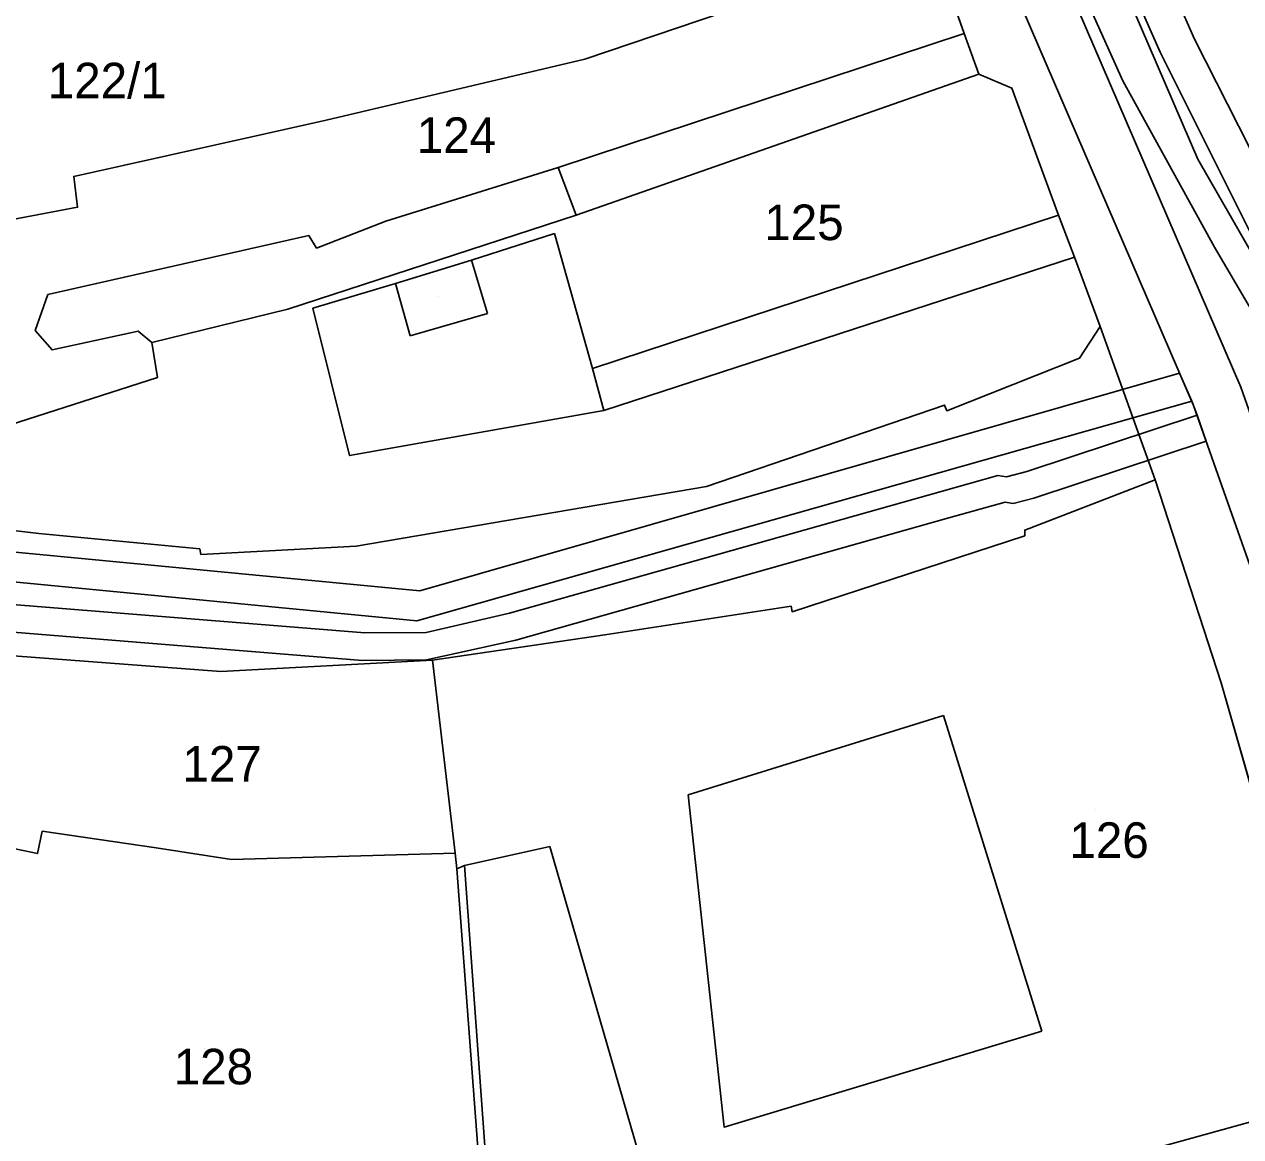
# Model space of a CAD drawing. Extents: x -263423 to -261326, y -1240067 to -1237864.
# Drawn here: x -262808 to -262739.6, y -1239820.5 to -1239757.9 of the extents above; entities that cross this region are included whole.
import ezdxf

# ---------------------------------------------------------------- set-up
doc = ezdxf.new("R2010")
doc.units = 0
for name, color, linetype in [('body_kn', 7, 'Continuous'), ('kladpar_druhypozemkov', 7, 'Continuous'), ('kladpar_hranice', 7, 'Continuous'), ('kladpar_parcelnecisla', 7, 'Continuous'), ('kladpar_plochy', 7, 'Continuous'), ('tarchy_linie', 7, 'Continuous'), ('zappar_hrandruhpozemk', 7, 'Continuous')]:
    doc.layers.add(name, color=color, linetype=linetype)

msp = doc.modelspace()

# ---------------------------------------------------------------- linework, layer by layer
at = {"layer": 'body_kn'}
for p, q in [((-262755.17, -1239758.45), (-262755.17, -1239758.45)), ((-262755.17, -1239758.45), (-262755.17, -1239758.45)), ((-262742.22, -1239758.77), (-262742.22, -1239758.77)), ((-262776.5, -1239759.89), (-262776.5, -1239759.89)), ((-262776.5, -1239759.89), (-262776.5, -1239759.89)), ((-262744.15, -1239759.51), (-262744.15, -1239759.51)), ((-262754.35, -1239760.75), (-262754.35, -1239760.75)), ((-262746.26, -1239761.11), (-262746.26, -1239761.11)), ((-262752.5, -1239761.52), (-262752.5, -1239761.52)), ((-262791.05, -1239763.32), (-262791.05, -1239763.32)), ((-262794.48, -1239764.1), (-262794.48, -1239764.1)), ((-262778, -1239765.99), (-262778, -1239765.99)), ((-262778, -1239765.99), (-262778, -1239765.99)), ((-262742.03, -1239765.52), (-262742.03, -1239765.52)), ((-262805.24, -1239766.49), (-262805.24, -1239766.49)), ((-262805.03, -1239768.22), (-262805.03, -1239768.22)), ((-262776.99, -1239768.67), (-262776.99, -1239768.67)), ((-262776.99, -1239768.67), (-262776.99, -1239768.67)), ((-262749.86, -1239768.67), (-262749.86, -1239768.67)), ((-262787.7, -1239769), (-262787.7, -1239769)), ((-262792.03, -1239769.81), (-262792.03, -1239769.81)), ((-262778.21, -1239769.69), (-262778.21, -1239769.69)), ((-262791.59, -1239770.52), (-262791.59, -1239770.52)), ((-262741.1, -1239770.47), (-262741.1, -1239770.47)), ((-262782.87, -1239771.19), (-262782.87, -1239771.19)), ((-262748.97, -1239771.03), (-262748.97, -1239771.03)), ((-262748.97, -1239771.03), (-262748.97, -1239771.03)), ((-262787.14, -1239772.51), (-262787.14, -1239772.51)), ((-262787.14, -1239772.51), (-262787.14, -1239772.51)), ((-262806.7, -1239773.12), (-262806.7, -1239773.12)), ((-262793.2, -1239773.95), (-262793.2, -1239773.95)), ((-262791.8, -1239773.89), (-262791.8, -1239773.89)), ((-262791.8, -1239773.89), (-262791.8, -1239773.89)), ((-262781.98, -1239774.19), (-262781.98, -1239774.19)), ((-262747.52, -1239774.93), (-262747.52, -1239774.93)), ((-262807.41, -1239775.16), (-262807.41, -1239775.16)), ((-262801.61, -1239775.18), (-262801.61, -1239775.18)), ((-262786.32, -1239775.45), (-262786.32, -1239775.45)), ((-262806.46, -1239776.24), (-262806.46, -1239776.24)), ((-262800.85, -1239775.82), (-262800.85, -1239775.82)), ((-262748.68, -1239776.7), (-262748.68, -1239776.7)), ((-262776.07, -1239777.28), (-262776.07, -1239777.28)), ((-262743.06, -1239777.55), (-262743.06, -1239777.55)), ((-262800.54, -1239777.8), (-262800.54, -1239777.8)), ((-262775.44, -1239779.64), (-262775.44, -1239779.64)), ((-262756.27, -1239779.34), (-262756.27, -1239779.34)), ((-262756.14, -1239779.66), (-262756.14, -1239779.66)), ((-262742.38, -1239779.12), (-262742.38, -1239779.12)), ((-262742.27, -1239779.37), (-262742.27, -1239779.37)), ((-262742.08, -1239779.91), (-262742.08, -1239779.91)), ((-262741.57, -1239781.37), (-262741.57, -1239781.37)), ((-262789.73, -1239782.18), (-262789.73, -1239782.18)), ((-262751.64, -1239783.07), (-262751.64, -1239783.07)), ((-262753.28, -1239783.31), (-262753.28, -1239783.31)), ((-262752.8, -1239783.37), (-262752.8, -1239783.37)), ((-262744.44, -1239783.54), (-262744.44, -1239783.54)), ((-262769.66, -1239783.93), (-262769.66, -1239783.93)), ((-262756.46, -1239784.2), (-262756.46, -1239784.2)), ((-262752.86, -1239784.8), (-262752.86, -1239784.8)), ((-262752.41, -1239784.87), (-262752.41, -1239784.87)), ((-262751.25, -1239784.57), (-262751.25, -1239784.57)), ((-262756.04, -1239785.69), (-262756.04, -1239785.69)), ((-262807.2, -1239786.56), (-262807.2, -1239786.56)), ((-262751.77, -1239786.37), (-262751.77, -1239786.37)), ((-262751.77, -1239786.69), (-262751.77, -1239786.69)), ((-262751.77, -1239786.69), (-262751.77, -1239786.69)), ((-262798.16, -1239787.43), (-262798.16, -1239787.43)), ((-262798.09, -1239787.75), (-262798.09, -1239787.75)), ((-262789.36, -1239787.28), (-262789.36, -1239787.28)), ((-262785.79, -1239789.79), (-262785.79, -1239789.79)), ((-262764.91, -1239790.65), (-262764.91, -1239790.65)), ((-262780.73, -1239791.05), (-262780.73, -1239791.05)), ((-262764.85, -1239790.96), (-262764.85, -1239790.96)), ((-262785.95, -1239791.48), (-262785.95, -1239791.48)), ((-262788.88, -1239792.15), (-262788.88, -1239792.15)), ((-262785.42, -1239792.12), (-262785.42, -1239792.12)), ((-262780.39, -1239792.56), (-262780.39, -1239792.56)), ((-262775.37, -1239792.25), (-262775.37, -1239792.25)), ((-262789, -1239793.7), (-262789, -1239793.7)), ((-262785.41, -1239793.67), (-262785.41, -1239793.67)), ((-262785.06, -1239793.68), (-262785.06, -1239793.68)), ((-262796.97, -1239794.32), (-262796.97, -1239794.32)), ((-262796.97, -1239794.32), (-262796.97, -1239794.32)), ((-262740.72, -1239794.96), (-262740.72, -1239794.96)), ((-262756.34, -1239796.8), (-262756.34, -1239796.8)), ((-262770.69, -1239801.26), (-262770.69, -1239801.26)), ((-262770.69, -1239801.26), (-262770.69, -1239801.26)), ((-262807.01, -1239803.29), (-262807.01, -1239803.29)), ((-262800.61, -1239804.24), (-262800.61, -1239804.24)), ((-262778.47, -1239804.16), (-262778.47, -1239804.16)), ((-262807.28, -1239804.56), (-262807.28, -1239804.56)), ((-262796.38, -1239804.89), (-262796.38, -1239804.89)), ((-262796.38, -1239804.89), (-262796.38, -1239804.89)), ((-262783.8, -1239804.54), (-262783.8, -1239804.54)), ((-262783.7, -1239805.41), (-262783.7, -1239805.41)), ((-262783.7, -1239805.41), (-262783.7, -1239805.41)), ((-262783.26, -1239805.22), (-262783.26, -1239805.22)), ((-262750.8, -1239814.54), (-262750.8, -1239814.54)), ((-262768.66, -1239819.94), (-262768.66, -1239819.94))]:
    msp.add_line(p, q, dxfattribs=at)
at = {"layer": 'kladpar_druhypozemkov'}
for p, q in [((-262802.68, -1239759.77), (-262802.68, -1239759.77)), ((-262783.98, -1239762.87), (-262783.98, -1239762.87)), ((-262764.48, -1239768.17), (-262764.48, -1239768.17)), ((-262784.73, -1239773.22), (-262784.73, -1239773.22)), ((-262797.08, -1239798.39), (-262797.08, -1239798.39)), ((-262747.78, -1239802.1), (-262747.78, -1239802.1)), ((-262797.88, -1239815.5), (-262797.88, -1239815.5))]:
    msp.add_line(p, q, dxfattribs=at)
at = {"layer": 'kladpar_hranice'}
for points in [[(-262819.26, -1239758.47), (-262800.19, -1239752.89), (-262797.7, -1239752.2), (-262787.75, -1239749.25), (-262787.43, -1239749.13), (-262782.39, -1239747.56), (-262764.98, -1239741.91), (-262761.47, -1239740.71), (-262759.7, -1239745.5), (-262758.95, -1239747.67), (-262756.99, -1239753.28), (-262776.5, -1239759.89), (-262791.05, -1239763.32), (-262794.48, -1239764.1), (-262805.24, -1239766.49), (-262805.03, -1239768.22), (-262813.14, -1239769.76), (-262811.51, -1239781.32), (-262813.94, -1239781.75), (-262815.81, -1239772.06), (-262819.26, -1239758.47)], [(-262776.5, -1239759.89), (-262756.99, -1239753.28), (-262755.17, -1239758.45), (-262754.35, -1239760.75), (-262776.99, -1239768.67), (-262793.2, -1239773.95), (-262800.85, -1239775.82), (-262800.54, -1239777.8), (-262811.51, -1239781.32), (-262813.14, -1239769.76), (-262805.03, -1239768.22), (-262805.24, -1239766.49), (-262794.48, -1239764.1), (-262791.05, -1239763.32), (-262776.5, -1239759.89)], [(-262737.14, -1239807.47), (-262740.72, -1239794.96), (-262744.44, -1239783.54), (-262747.52, -1239774.93), (-262748.97, -1239771.03), (-262749.86, -1239768.67), (-262752.5, -1239761.52), (-262754.35, -1239760.75), (-262755.17, -1239758.45), (-262756.99, -1239753.28)], [(-262776.99, -1239768.67), (-262754.35, -1239760.75), (-262752.5, -1239761.52), (-262749.86, -1239768.67), (-262748.97, -1239771.03), (-262747.52, -1239774.93), (-262748.68, -1239776.7), (-262756.14, -1239779.66), (-262756.27, -1239779.34), (-262769.66, -1239783.93), (-262789.36, -1239787.28), (-262798.09, -1239787.75), (-262798.16, -1239787.43), (-262807.2, -1239786.56), (-262818.47, -1239785.24)], [(-262811.51, -1239781.32), (-262800.54, -1239777.8), (-262800.85, -1239775.82), (-262793.2, -1239773.95), (-262776.99, -1239768.67)], [(-262818.47, -1239785.24), (-262807.2, -1239786.56), (-262798.16, -1239787.43), (-262798.09, -1239787.75), (-262789.36, -1239787.28), (-262769.66, -1239783.93), (-262756.27, -1239779.34), (-262756.14, -1239779.66), (-262748.68, -1239776.7), (-262747.52, -1239774.93), (-262744.44, -1239783.54), (-262751.77, -1239786.37), (-262751.77, -1239786.69), (-262764.85, -1239790.96), (-262764.91, -1239790.65), (-262775.37, -1239792.25), (-262785.06, -1239793.68), (-262796.97, -1239794.32), (-262808.63, -1239793.44)], [(-262751.77, -1239786.69), (-262751.77, -1239786.37), (-262744.44, -1239783.54), (-262740.72, -1239794.96), (-262737.14, -1239807.47), (-262733.56, -1239818.12), (-262770.29, -1239828.28), (-262771.57, -1239828.53), (-262775.26, -1239828.89), (-262777.05, -1239829.08), (-262781.89, -1239829.56), (-262782.25, -1239824.59), (-262783.7, -1239805.41), (-262783.8, -1239804.54), (-262785.06, -1239793.68), (-262775.37, -1239792.25), (-262764.91, -1239790.65), (-262764.85, -1239790.96), (-262751.77, -1239786.69)], [(-262796.97, -1239794.32), (-262785.06, -1239793.68), (-262783.8, -1239804.54), (-262796.38, -1239804.89), (-262800.61, -1239804.24), (-262807.01, -1239803.29), (-262807.28, -1239804.56), (-262809.46, -1239804.1), (-262808.63, -1239793.44), (-262796.97, -1239794.32)], [(-262796.38, -1239804.89), (-262783.8, -1239804.54), (-262783.7, -1239805.41), (-262782.25, -1239824.59), (-262781.89, -1239829.56), (-262789.54, -1239831.5), (-262808.46, -1239830.27), (-262811.52, -1239829.55), (-262809.71, -1239807.52), (-262809.57, -1239805.54), (-262809.46, -1239804.1), (-262807.28, -1239804.56), (-262807.01, -1239803.29), (-262800.61, -1239804.24), (-262796.38, -1239804.89)], [(-262733.56, -1239818.12), (-262726.83, -1239838.6), (-262752.66, -1239846.9), (-262767.97, -1239851.8), (-262769.73, -1239845.8), (-262772.74, -1239836.29), (-262775.26, -1239828.89), (-262771.57, -1239828.53), (-262770.29, -1239828.28), (-262733.56, -1239818.12)]]:
    msp.add_lwpolyline(points, dxfattribs=at)
at = {"layer": 'kladpar_plochy'}
for p, q in [((-262755.17, -1239758.45), (-262756.99, -1239753.28)), ((-262754.35, -1239760.75), (-262755.17, -1239758.45)), ((-262752.5, -1239761.52), (-262754.35, -1239760.75)), ((-262749.86, -1239768.67), (-262752.5, -1239761.52)), ((-262748.97, -1239771.03), (-262749.86, -1239768.67)), ((-262747.52, -1239774.93), (-262748.97, -1239771.03)), ((-262744.44, -1239783.54), (-262747.52, -1239774.93)), ((-262740.72, -1239794.96), (-262744.44, -1239783.54)), ((-262737.14, -1239807.47), (-262740.72, -1239794.96))]:
    msp.add_line(p, q, dxfattribs=at)
for points in [[(-262819.26, -1239758.47), (-262800.19, -1239752.89), (-262797.7, -1239752.2), (-262787.75, -1239749.25), (-262787.43, -1239749.13), (-262782.39, -1239747.56), (-262764.98, -1239741.91), (-262761.47, -1239740.71), (-262759.7, -1239745.5), (-262758.95, -1239747.67), (-262756.99, -1239753.28), (-262776.5, -1239759.89), (-262791.05, -1239763.32), (-262794.48, -1239764.1), (-262805.24, -1239766.49), (-262805.03, -1239768.22), (-262813.14, -1239769.76), (-262811.51, -1239781.32), (-262813.94, -1239781.75), (-262815.81, -1239772.06)], [(-262776.5, -1239759.89), (-262756.99, -1239753.28), (-262755.17, -1239758.45), (-262754.35, -1239760.75), (-262776.99, -1239768.67), (-262793.2, -1239773.95), (-262800.85, -1239775.82), (-262800.54, -1239777.8), (-262811.51, -1239781.32), (-262813.14, -1239769.76), (-262805.03, -1239768.22), (-262805.24, -1239766.49), (-262794.48, -1239764.1), (-262791.05, -1239763.32)], [(-262776.99, -1239768.67), (-262754.35, -1239760.75), (-262752.5, -1239761.52), (-262749.86, -1239768.67), (-262748.97, -1239771.03), (-262747.52, -1239774.93), (-262748.68, -1239776.7), (-262756.14, -1239779.66), (-262756.27, -1239779.34), (-262769.66, -1239783.93), (-262789.36, -1239787.28), (-262798.09, -1239787.75), (-262798.16, -1239787.43), (-262807.2, -1239786.56), (-262818.47, -1239785.24), (-262828.53, -1239782.96), (-262829.42, -1239782.57), (-262817.95, -1239781.99), (-262815.45, -1239781.84), (-262813.94, -1239781.75), (-262811.51, -1239781.32), (-262800.54, -1239777.8), (-262800.85, -1239775.82), (-262793.2, -1239773.95)], [(-262751.77, -1239786.69), (-262751.77, -1239786.37), (-262744.44, -1239783.54), (-262740.72, -1239794.96), (-262737.14, -1239807.47), (-262733.56, -1239818.12), (-262770.29, -1239828.28), (-262771.57, -1239828.53), (-262775.26, -1239828.89), (-262777.05, -1239829.08), (-262781.89, -1239829.56), (-262782.25, -1239824.59), (-262783.7, -1239805.41), (-262783.8, -1239804.54), (-262785.06, -1239793.68), (-262775.37, -1239792.25), (-262764.91, -1239790.65), (-262764.85, -1239790.96)], [(-262796.97, -1239794.32), (-262785.06, -1239793.68), (-262783.8, -1239804.54), (-262796.38, -1239804.89), (-262800.61, -1239804.24), (-262807.01, -1239803.29), (-262807.28, -1239804.56), (-262809.46, -1239804.1), (-262808.63, -1239793.44)], [(-262796.38, -1239804.89), (-262783.8, -1239804.54), (-262783.7, -1239805.41), (-262782.25, -1239824.59), (-262781.89, -1239829.56), (-262789.54, -1239831.5), (-262808.46, -1239830.27), (-262811.52, -1239829.55), (-262809.71, -1239807.52), (-262809.57, -1239805.54), (-262809.46, -1239804.1), (-262807.28, -1239804.56), (-262807.01, -1239803.29), (-262800.61, -1239804.24)], [(-262733.56, -1239818.12), (-262726.83, -1239838.6), (-262752.66, -1239846.9), (-262767.97, -1239851.8), (-262769.73, -1239845.8), (-262772.74, -1239836.29), (-262775.26, -1239828.89), (-262771.57, -1239828.53), (-262770.29, -1239828.28)]]:
    msp.add_lwpolyline(points, close=True, dxfattribs=at)
msp.add_lwpolyline([(-262818.47, -1239785.24), (-262807.2, -1239786.56), (-262798.16, -1239787.43), (-262798.09, -1239787.75), (-262789.36, -1239787.28), (-262769.66, -1239783.93), (-262756.27, -1239779.34), (-262756.14, -1239779.66), (-262748.68, -1239776.7), (-262747.52, -1239774.93), (-262744.44, -1239783.54), (-262751.77, -1239786.37), (-262751.77, -1239786.69), (-262764.85, -1239790.96), (-262764.91, -1239790.65), (-262775.37, -1239792.25), (-262785.06, -1239793.68), (-262796.97, -1239794.32), (-262808.63, -1239793.44)], dxfattribs=at)
at = {"layer": 'tarchy_linie'}
for points in [[(-262706.54, -1239880.67), (-262742.27, -1239779.37), (-262780.81, -1239690), (-262819.34, -1239601.25), (-262816.79, -1239600.49), (-262817.29, -1239598.81), (-262817.32, -1239598.72), (-262815.09, -1239597.98), (-262814.98, -1239597.94), (-262815.48, -1239596.45), (-262815.98, -1239594.96), (-262818.17, -1239595.69), (-262820.83, -1239596.57), (-262845.98, -1239506.9)], [(-262735.26, -1239777.31), (-262742.03, -1239765.52), (-262775.57, -1239687.74), (-262811.81, -1239604.28), (-262814.73, -1239592.68), (-262817.65, -1239581.52), (-262822.24, -1239563.13)], [(-262736.62, -1239778.1), (-262741.1, -1239770.47), (-262746.26, -1239761.11), (-262751.59, -1239749.24), (-262753.75, -1239744.39), (-262756.57, -1239737.71), (-262761.11, -1239727.02), (-262763.9, -1239720.28), (-262768.21, -1239710.04), (-262772.17, -1239700.1), (-262776, -1239690.78), (-262780.26, -1239681.08), (-262784.83, -1239671.23), (-262789.11, -1239661.86), (-262793.12, -1239652.78), (-262797.39, -1239643.05), (-262801.85, -1239633.31), (-262808.04, -1239619.61), (-262811.66, -1239610.43), (-262813.83, -1239602.97), (-262815.09, -1239597.98)], [(-262657.08, -1239929.21), (-262646.38, -1239963), (-262674.82, -1239975.1), (-262703.83, -1239879.78), (-262739.61, -1239778.33), (-262778.19, -1239688.87), (-262817.29, -1239598.81)], [(-263076.78, -1239674.94), (-263067.73, -1239689.43), (-263061.59, -1239698.97), (-263048.27, -1239722.8), (-262993, -1239743.37), (-262958.92, -1239752.71), (-262923.54, -1239762), (-262867.86, -1239773.48), (-262824.56, -1239787.75), (-262785.95, -1239791.48), (-262742.38, -1239779.12)], [(-262940.14, -1239759.32), (-262928.37, -1239762.28), (-262917.86, -1239764.95), (-262902.23, -1239768.95), (-262884.95, -1239770.75), (-262884.36, -1239770.87), (-262883.78, -1239770.73), (-262869.45, -1239773.93), (-262850.93, -1239779.31), (-262843.22, -1239781.94), (-262829.93, -1239786.66), (-262823.34, -1239788.76), (-262817.45, -1239789.44), (-262809.15, -1239790.52), (-262788.88, -1239792.15), (-262785.42, -1239792.12), (-262780.73, -1239791.05), (-262756.46, -1239784.2), (-262753.28, -1239783.31), (-262752.8, -1239783.37), (-262751.64, -1239783.07), (-262742.08, -1239779.91)], [(-262866.56, -1239772.12), (-262824.03, -1239786.14), (-262785.79, -1239789.79), (-262743.06, -1239777.55), (-262742.38, -1239779.12), (-262742.08, -1239779.91), (-262741.57, -1239781.37), (-262751.25, -1239784.57), (-262752.41, -1239784.87), (-262752.86, -1239784.8), (-262756.04, -1239785.69), (-262780.39, -1239792.56), (-262785.41, -1239793.67), (-262789, -1239793.7), (-262809.35, -1239792.06), (-262817.63, -1239790.98), (-262823.81, -1239790.24), (-262830.45, -1239788.12), (-262843.72, -1239783.41), (-262851.36, -1239780.8)]]:
    msp.add_lwpolyline(points, dxfattribs=at)
at = {"layer": 'zappar_hrandruhpozemk'}
for p, q in [((-262755.17, -1239758.45), (-262778, -1239765.99)), ((-262778, -1239765.99), (-262787.7, -1239769)), ((-262776.99, -1239768.67), (-262778, -1239765.99)), ((-262776.07, -1239777.28), (-262749.86, -1239768.67)), ((-262778.21, -1239769.69), (-262776.07, -1239777.28)), ((-262781.98, -1239774.19), (-262782.87, -1239771.19)), ((-262748.97, -1239771.03), (-262775.44, -1239779.64)), ((-262787.14, -1239772.51), (-262786.32, -1239775.45)), ((-262806.7, -1239773.12), (-262807.41, -1239775.16)), ((-262786.32, -1239775.45), (-262781.98, -1239774.19)), ((-262770.69, -1239801.26), (-262756.34, -1239796.8)), ((-262756.34, -1239796.8), (-262750.8, -1239814.54)), ((-262778.47, -1239804.16), (-262773.07, -1239822.79)), ((-262781.87, -1239824.53), (-262783.26, -1239805.22))]:
    msp.add_line(p, q, dxfattribs=at)
for points in [[(-262752.45, -1239735.52), (-262742.22, -1239758.77), (-262737.25, -1239768.56), (-262731.89, -1239777.14)], [(-262754.38, -1239736.37), (-262744.15, -1239759.51), (-262739.05, -1239769.7)], [(-262787.7, -1239769), (-262791.59, -1239770.52), (-262792.03, -1239769.81), (-262806.7, -1239773.12)], [(-262791.8, -1239773.89), (-262787.14, -1239772.51), (-262782.87, -1239771.19), (-262778.21, -1239769.69)], [(-262776.07, -1239777.28), (-262775.44, -1239779.64), (-262789.73, -1239782.18), (-262791.8, -1239773.89)], [(-262807.41, -1239775.16), (-262806.46, -1239776.24), (-262801.61, -1239775.18), (-262800.85, -1239775.82)], [(-262750.8, -1239814.54), (-262768.66, -1239819.94), (-262770.69, -1239801.26)], [(-262783.7, -1239805.41), (-262783.26, -1239805.22), (-262778.47, -1239804.16)]]:
    msp.add_lwpolyline(points, dxfattribs=at)

# ---------------------------------------------------------------- texts
at = {"layer": 'kladpar_parcelnecisla'}
for s, p in [('122/1', (-262806.703, -1239762.1)), ('124', (-262785.956, -1239765.17)), ('125', (-262766.411, -1239770.07)), ('127', (-262799.129, -1239800.51)), ('126', (-262749.256, -1239804.8)), ('128', (-262799.62, -1239817.53))]:
    msp.add_text(s, height=2, dxfattribs=at).set_placement(p)

doc.saveas('drawing.dxf')
